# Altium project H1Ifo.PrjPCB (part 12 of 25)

## Sheet IfoIsc6.SchDoc: D1800185
size C; Engineer: Daniel Sigg; DocumentNumber: 11; Revision: 4; SheetNumber: 11; SheetTotal: 11
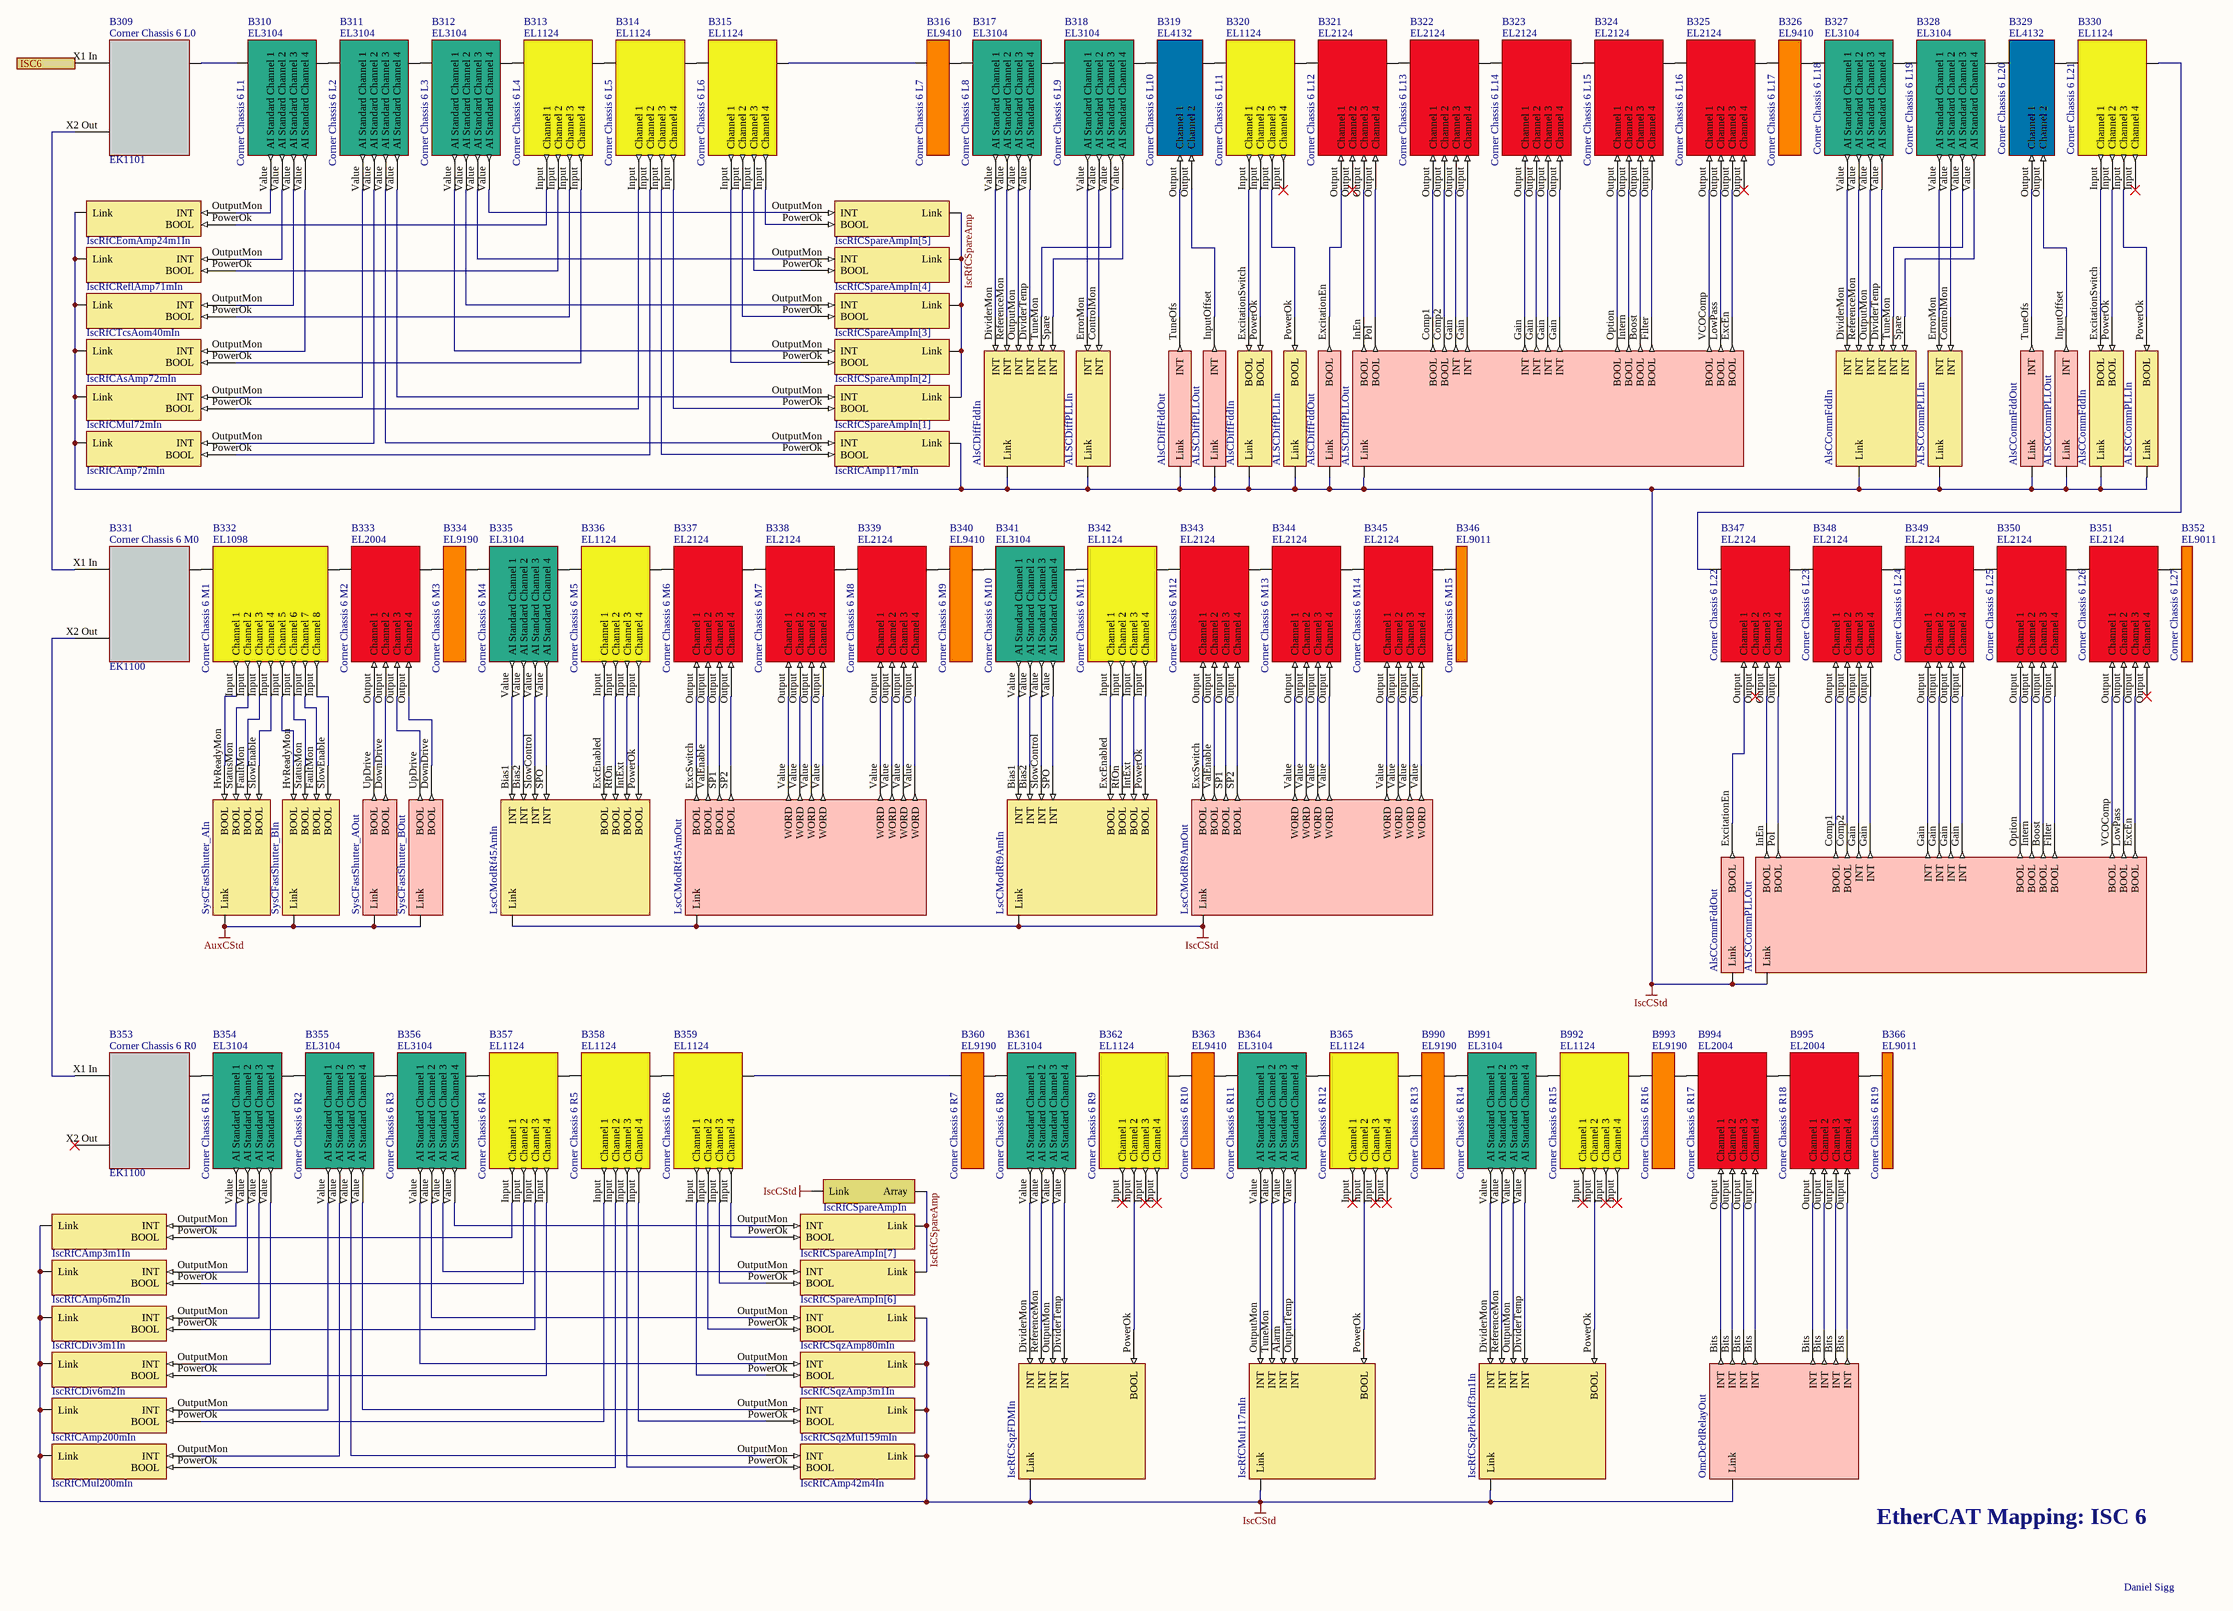
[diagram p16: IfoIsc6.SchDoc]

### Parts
B309  Corner Chassis 6 L0  Part Number: EK1101  (mechanical)
B310  Corner Chassis 6 L1  Part Number: EL3104  (mechanical)
B311  Corner Chassis 6 L2  Part Number: EL3104  (mechanical)
B312  Corner Chassis 6 L3  Part Number: EL3104  (mechanical)
B313  Corner Chassis 6 L4  Part Number: EL1124  (mechanical)
B314  Corner Chassis 6 L5  Part Number: EL1124  (mechanical)
B315  Corner Chassis 6 L6  Part Number: EL1124  (mechanical)
B316  Corner Chassis 6 L7  Part Number: EL9410  (mechanical)
B317  Corner Chassis 6 L8  Part Number: EL3104  (mechanical)
B318  Corner Chassis 6 L9  Part Number: EL3104  (mechanical)
B319  Corner Chassis 6 L10  Part Number: EL4132  (mechanical)
B320  Corner Chassis 6 L11  Part Number: EL1124  (mechanical)
B321  Corner Chassis 6 L12  Part Number: EL2124  (mechanical)
B322  Corner Chassis 6 L13  Part Number: EL2124  (mechanical)
B323  Corner Chassis 6 L14  Part Number: EL2124  (mechanical)
B324  Corner Chassis 6 L15  Part Number: EL2124  (mechanical)
B325  Corner Chassis 6 L16  Part Number: EL2124  (mechanical)
B326  Corner Chassis 6 L17  Part Number: EL9410  (mechanical)
B327  Corner Chassis 6 L18  Part Number: EL3104  (mechanical)
B328  Corner Chassis 6 L19  Part Number: EL3104  (mechanical)
B329  Corner Chassis 6 L20  Part Number: EL4132  (mechanical)
B330  Corner Chassis 6 L21  Part Number: EL1124  (mechanical)
B331  Corner Chassis 6 M0  Part Number: EK1100  (mechanical)
B332  Corner Chassis 6 M1  Part Number: EL1098  (mechanical)
B333  Corner Chassis 6 M2  Part Number: EL2004  (mechanical)
B334  Corner Chassis 6 M3  Part Number: EL9190  (mechanical)
B335  Corner Chassis 6 M4  Part Number: EL3104  (mechanical)
B336  Corner Chassis 6 M5  Part Number: EL1124  (mechanical)
B337  Corner Chassis 6 M6  Part Number: EL2124  (mechanical)
B338  Corner Chassis 6 M7  Part Number: EL2124  (mechanical)
B339  Corner Chassis 6 M8  Part Number: EL2124  (mechanical)
B340  Corner Chassis 6 M9  Part Number: EL9410  (mechanical)
B341  Corner Chassis 6 M10  Part Number: EL3104  (mechanical)
B342  Corner Chassis 6 M11  Part Number: EL1124  (mechanical)
B343  Corner Chassis 6 M12  Part Number: EL2124  (mechanical)
B344  Corner Chassis 6 M13  Part Number: EL2124  (mechanical)
B345  Corner Chassis 6 M14  Part Number: EL2124  (mechanical)
B346  Corner Chassis 6 M15  Part Number: EL9011  (mechanical)
B347  Corner Chassis 6 L22  Part Number: EL2124  (mechanical)
B348  Corner Chassis 6 L23  Part Number: EL2124  (mechanical)
B349  Corner Chassis 6 L24  Part Number: EL2124  (mechanical)
B350  Corner Chassis 6 L25  Part Number: EL2124  (mechanical)
B351  Corner Chassis 6 L26  Part Number: EL2124  (mechanical)
B352  Corner Chassis 6 L27  Part Number: EL9011  (mechanical)
B353  Corner Chassis 6 R0  Part Number: EK1100  (mechanical)
B354  Corner Chassis 6 R1  Part Number: EL3104  (mechanical)
B355  Corner Chassis 6 R2  Part Number: EL3104  (mechanical)
B356  Corner Chassis 6 R3  Part Number: EL3104  (mechanical)
B357  Corner Chassis 6 R4  Part Number: EL1124  (mechanical)
B358  Corner Chassis 6 R5  Part Number: EL1124  (mechanical)
B359  Corner Chassis 6 R6  Part Number: EL1124  (mechanical)
B360  Corner Chassis 6 R7  Part Number: EL9190  (mechanical)
B361  Corner Chassis 6 R8  Part Number: EL3104  (mechanical)
B362  Corner Chassis 6 R9  Part Number: EL1124  (mechanical)
B363  Corner Chassis 6 R10  Part Number: EL9410  (mechanical)
B364  Corner Chassis 6 R11  Part Number: EL3104  (mechanical)
B365  Corner Chassis 6 R12  Part Number: EL1124  (mechanical)
B366  Corner Chassis 6 R19  Part Number: EL9011  (mechanical)
B990  Corner Chassis 6 R13  Part Number: EL9190  (mechanical)
B991  Corner Chassis 6 R14  Part Number: EL3104  (mechanical)
B992  Corner Chassis 6 R15  Part Number: EL1124  (mechanical)
B993  Corner Chassis 6 R16  Part Number: EL9190  (mechanical)
B994  Corner Chassis 6 R17  Part Number: EL2004  (mechanical)
B995  Corner Chassis 6 R18  Part Number: EL2004  (mechanical)
V272  AlsCDiffFddIn  (parts A,B of 2)  (no BOM)
V273  AlsCDiffFddOut  (parts A,B of 2)  (no BOM)
V274  AlsCCommFddIn  (parts A,B of 2)  (no BOM)
V275  AlsCCommFddOut  (parts A,B of 2)  (no BOM)
V276  ALSCDiffPLLIn  (parts A,B of 2)  (no BOM)
V277  ALSCDiffPLLOut  (parts A,B of 2)  (no BOM)
V278  ALSCCommPLLIn  (parts A,B of 2)  (no BOM)
V279  ALSCCommPLLOut  (parts A,B of 2)  (no BOM)
V406  IscRfCEomAmp24m1In  (no BOM)
V407  IscRfCSpareAmpIn[5]  (no BOM)
V408  IscRfCReflAmp71mIn  (no BOM)
V409  IscRfCSpareAmpIn[4]  (no BOM)
V412  IscRfCTcsAom40mIn  (no BOM)
V413  IscRfCSpareAmpIn[3]  (no BOM)
V414  IscRfCAsAmp72mIn  (no BOM)
V415  IscRfCSpareAmpIn[2]  (no BOM)
V416  IscRfCMul72mIn  (no BOM)
V417  IscRfCSpareAmpIn[1]  (no BOM)
V418  IscRfCAmp72mIn  (no BOM)
V419  IscRfCAmp117mIn  (no BOM)
V420  SysCFastShutter_AIn  (no BOM)
V421  SysCFastShutter_AOut  (no BOM)
V422  LscCModRf45AmIn  (no BOM)
V424  LscCModRf45AmOut  (no BOM)
V426  LscCModRf9AmIn  (no BOM)
V428  LscCModRf9AmOut  (no BOM)
V429  IscRfCSpareAmpIn  (no BOM)
V430  IscRfCAmp3m1In  (no BOM)
V431  IscRfCSpareAmpIn[7]  (no BOM)
V432  IscRfCAmp6m2In  (no BOM)
V433  IscRfCSpareAmpIn[6]  (no BOM)
V434  IscRfCDiv3m1In  (no BOM)
V435  IscRfCSqzAmp80mIn  (no BOM)
V436  IscRfCDiv6m2In  (no BOM)
V438  IscRfCSqzAmp3m1In  (no BOM)
V439  IscRfCSqzFDMIn  (no BOM)
V440  IscRfCMul117mIn  (no BOM)
V441  IscRfCAmp200mIn  (no BOM)
V442  IscRfCSqzMul159mIn  (no BOM)
V443  IscRfCMul200mIn  (no BOM)
V444  IscRfCAmp42m4In  (no BOM)
V900  IscRfCSqzPickoff3m1In  (no BOM)
V901  OmcDcPdRelayOut  (no BOM)
V908  SysCFastShutter_BIn  (no BOM)
V909  SysCFastShutter_BOut  (no BOM)

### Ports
ISC6

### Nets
AuxCStd: V420.1(Link) V421.1(Link) V908.1(Link) V909.1(Link)
IscCStd: V272.0(Link) V272.1(Link) V273.0(Link) V273.1(Link) V274.0(Link) V274.1(Link) V275.0(Link) V275.1(Link) V276.0(Link) V276.1(Link) V277.0(Link) V277.1(Link) V278.0(Link) V278.1(Link) V279.0(Link) V279.1(Link) V406.?1(Link) V408.?1(Link) V412.?1(Link) V414.?1(Link) V416.?1(Link) V418.?1(Link) V419.?1(Link) V422.0(Link) V424.?1(Link) V426.0(Link) V428.?1(Link) V429.?1(Link) V430.?1(Link) V432.?1(Link) V434.?1(Link) V435.?1(Link) V436.?1(Link) V438.?1(Link) V439.0(Link) V440.0(Link) V441.?1(Link) V442.?1(Link) V443.?1(Link) V444.?1(Link) V900.0(Link) V901.1(Link)
IscRfCSpareAmp: V407.?1(Link) V409.?1(Link) V413.?1(Link) V415.?1(Link) V417.?1(Link) V429.?2(Array) V431.?1(Link) V433.?1(Link)
NetB275_X2 Out: B309.X1_In(A) ; port ISC6
NetB309_Ebus: B309.Ebus(B) B310.Ebus(A)
NetB309_X2 Out: B309.X2_Out(C) B331.X1_In(A)
NetB310_Ebus: B310.Ebus(B) B311.Ebus(A)
NetB310_Value: B310.Value(AI_Standard_Channel_1) V406.OutputMon(INT)
NetB310_Value: B310.Value(AI_Standard_Channel_2) V408.OutputMon(INT)  [a separate net that carries the same name]
NetB310_Value: B310.Value(AI_Standard_Channel_3) V412.OutputMon(INT)  [a separate net that carries the same name]
NetB310_Value: B310.Value(AI_Standard_Channel_4) V414.OutputMon(INT)  [a separate net that carries the same name]
NetB311_Ebus: B311.Ebus(B) B312.Ebus(A)
NetB311_Value: B311.Value(AI_Standard_Channel_1) V416.OutputMon(INT)
NetB311_Value: B311.Value(AI_Standard_Channel_2) V418.OutputMon(INT)  [a separate net that carries the same name]
NetB311_Value: B311.Value(AI_Standard_Channel_3) V419.OutputMon(INT)  [a separate net that carries the same name]
NetB311_Value: B311.Value(AI_Standard_Channel_4) V417.OutputMon(INT)  [a separate net that carries the same name]
NetB312_Ebus: B312.Ebus(B) B313.Ebus(A)
NetB312_Value: B312.Value(AI_Standard_Channel_1) V415.OutputMon(INT)
NetB312_Value: B312.Value(AI_Standard_Channel_2) V413.OutputMon(INT)  [a separate net that carries the same name]
NetB312_Value: B312.Value(AI_Standard_Channel_3) V409.OutputMon(INT)  [a separate net that carries the same name]
NetB312_Value: B312.Value(AI_Standard_Channel_4) V407.OutputMon(INT)  [a separate net that carries the same name]
NetB313_Ebus: B313.Ebus(B) B314.Ebus(A)
NetB313_Input: B313.Input(Channel_1) V406.PowerOk(BOOL)
NetB313_Input: B313.Input(Channel_2) V408.PowerOk(BOOL)  [a separate net that carries the same name]
NetB313_Input: B313.Input(Channel_3) V412.PowerOk(BOOL)  [a separate net that carries the same name]
NetB313_Input: B313.Input(Channel_4) V414.PowerOk(BOOL)  [a separate net that carries the same name]
NetB314_Ebus: B314.Ebus(B) B315.Ebus(A)
NetB314_Input: B314.Input(Channel_1) V416.PowerOk(BOOL)
NetB314_Input: B314.Input(Channel_2) V418.PowerOk(BOOL)  [a separate net that carries the same name]
NetB314_Input: B314.Input(Channel_3) V419.PowerOk(BOOL)  [a separate net that carries the same name]
NetB314_Input: B314.Input(Channel_4) V417.PowerOk(BOOL)  [a separate net that carries the same name]
NetB315_Ebus: B315.Ebus(B) B316.Ebus(A)
NetB315_Input: B315.Input(Channel_1) V415.PowerOk(BOOL)
NetB315_Input: B315.Input(Channel_2) V413.PowerOk(BOOL)  [a separate net that carries the same name]
NetB315_Input: B315.Input(Channel_3) V409.PowerOk(BOOL)  [a separate net that carries the same name]
NetB315_Input: B315.Input(Channel_4) V407.PowerOk(BOOL)  [a separate net that carries the same name]
NetB316_Ebus: B316.Ebus(B) B317.Ebus(A)
NetB317_Ebus: B317.Ebus(B) B318.Ebus(A)
NetB317_Value: B317.Value(AI_Standard_Channel_1) V272.DividerMon(INT)
NetB317_Value: B317.Value(AI_Standard_Channel_2) V272.ReferenceMon(INT)  [a separate net that carries the same name]
NetB317_Value: B317.Value(AI_Standard_Channel_3) V272.OutputMon(INT)  [a separate net that carries the same name]
NetB317_Value: B317.Value(AI_Standard_Channel_4) V272.DividerTemp(INT)  [a separate net that carries the same name]
NetB318_Ebus: B318.Ebus(B) B319.Ebus(A)
NetB318_Value: B318.Value(AI_Standard_Channel_1) V276.ErrorMon(INT)
NetB318_Value: B318.Value(AI_Standard_Channel_2) V276.ControlMon(INT)  [a separate net that carries the same name]
NetB318_Value: B318.Value(AI_Standard_Channel_3) V272.TuneMon(INT)  [a separate net that carries the same name]
NetB318_Value: B318.Value(AI_Standard_Channel_4) V272.Spare(INT)  [a separate net that carries the same name]
NetB319_Ebus: B319.Ebus(B) B320.Ebus(A)
NetB319_Output: B319.Output(Channel_1) V273.TuneOfs(INT)
NetB319_Output: B319.Output(Channel_2) V277.InputOffset(INT)  [a separate net that carries the same name]
NetB320_Ebus: B320.Ebus(B) B321.Ebus(A)
NetB320_Input: B320.Input(Channel_1) V272.ExcitationSwitch(BOOL)
NetB320_Input: B320.Input(Channel_2) V272.PowerOk(BOOL)  [a separate net that carries the same name]
NetB320_Input: B320.Input(Channel_3) V276.PowerOk(BOOL)  [a separate net that carries the same name]
NetB321_Ebus: B321.Ebus(B) B322.Ebus(A)
NetB321_Output: B321.Output(Channel_1) V273.ExcitationEn(BOOL)
NetB321_Output: B321.Output(Channel_3) V277.InEn(BOOL)  [a separate net that carries the same name]
NetB321_Output: B321.Output(Channel_4) V277.Pol(BOOL)  [a separate net that carries the same name]
NetB322_Ebus: B322.Ebus(B) B323.Ebus(A)
NetB322_Output: B322.Output(Channel_1) V277.Comp1(BOOL)
NetB322_Output: B322.Output(Channel_2) V277.Comp2(BOOL)  [a separate net that carries the same name]
NetB322_Output: B322.Output(Channel_3) V277.Gain(INT)  [a separate net that carries the same name]
NetB322_Output: B322.Output(Channel_4) V277.Gain(INT)  [a separate net that carries the same name]
NetB323_Ebus: B323.Ebus(B) B324.Ebus(A)
NetB323_Output: B323.Output(Channel_1) V277.Gain(INT)
NetB323_Output: B323.Output(Channel_2) V277.Gain(INT)  [a separate net that carries the same name]
NetB323_Output: B323.Output(Channel_3) V277.Gain(INT)  [a separate net that carries the same name]
NetB323_Output: B323.Output(Channel_4) V277.Gain(INT)  [a separate net that carries the same name]
NetB324_Ebus: B324.Ebus(B) B325.Ebus(A)
NetB324_Output: B324.Output(Channel_1) V277.Option(BOOL)
NetB324_Output: B324.Output(Channel_2) V277.Intern(BOOL)  [a separate net that carries the same name]
NetB324_Output: B324.Output(Channel_3) V277.Boost(BOOL)  [a separate net that carries the same name]
NetB324_Output: B324.Output(Channel_4) V277.Filter(BOOL)  [a separate net that carries the same name]
NetB325_Ebus: B325.Ebus(B) B326.Ebus(A)
NetB325_Output: B325.Output(Channel_1) V277.VCOComp(BOOL)
NetB325_Output: B325.Output(Channel_2) V277.LowPass(BOOL)  [a separate net that carries the same name]
NetB325_Output: B325.Output(Channel_3) V277.ExcEn(BOOL)  [a separate net that carries the same name]
NetB326_Ebus: B326.Ebus(B) B327.Ebus(A)
NetB327_Ebus: B327.Ebus(B) B328.Ebus(A)
NetB327_Value: B327.Value(AI_Standard_Channel_1) V274.DividerMon(INT)
NetB327_Value: B327.Value(AI_Standard_Channel_2) V274.ReferenceMon(INT)  [a separate net that carries the same name]
NetB327_Value: B327.Value(AI_Standard_Channel_3) V274.OutputMon(INT)  [a separate net that carries the same name]
NetB327_Value: B327.Value(AI_Standard_Channel_4) V274.DividerTemp(INT)  [a separate net that carries the same name]
NetB328_Ebus: B328.Ebus(B) B329.Ebus(A)
NetB328_Value: B328.Value(AI_Standard_Channel_1) V278.ErrorMon(INT)
NetB328_Value: B328.Value(AI_Standard_Channel_2) V278.ControlMon(INT)  [a separate net that carries the same name]
NetB328_Value: B328.Value(AI_Standard_Channel_3) V274.TuneMon(INT)  [a separate net that carries the same name]
NetB328_Value: B328.Value(AI_Standard_Channel_4) V274.Spare(INT)  [a separate net that carries the same name]
NetB329_Ebus: B329.Ebus(B) B330.Ebus(A)
NetB329_Output: B329.Output(Channel_1) V275.TuneOfs(INT)
NetB329_Output: B329.Output(Channel_2) V279.InputOffset(INT)  [a separate net that carries the same name]
NetB330_Ebus: B330.Ebus(B) B347.Ebus(A)
NetB330_Input: B330.Input(Channel_1) V274.ExcitationSwitch(BOOL)
NetB330_Input: B330.Input(Channel_2) V274.PowerOk(BOOL)  [a separate net that carries the same name]
NetB330_Input: B330.Input(Channel_3) V278.PowerOk(BOOL)  [a separate net that carries the same name]
NetB331_Ebus: B331.Ebus(B) B332.Ebus(A)
NetB331_X2 Out: B331.X2_Out(C) B353.X1_In(A)
NetB332_Ebus: B332.Ebus(B) B333.Ebus(A)
NetB332_Input: B332.Input(Channel_1) V420.HvReadyMon(BOOL)
NetB332_Input: B332.Input(Channel_2) V420.StatusMon(BOOL)  [a separate net that carries the same name]
NetB332_Input: B332.Input(Channel_3) V420.FaultMon(BOOL)  [a separate net that carries the same name]
NetB332_Input: B332.Input(Channel_4) V420.SlowEnable(BOOL)  [a separate net that carries the same name]
NetB332_Input: B332.Input(Channel_5) V908.HvReadyMon(BOOL)  [a separate net that carries the same name]
NetB332_Input: B332.Input(Channel_6) V908.StatusMon(BOOL)  [a separate net that carries the same name]
NetB332_Input: B332.Input(Channel_7) V908.FaultMon(BOOL)  [a separate net that carries the same name]
NetB332_Input: B332.Input(Channel_8) V908.SlowEnable(BOOL)  [a separate net that carries the same name]
NetB333_Ebus: B333.Ebus(B) B334.Ebus(A)
NetB333_Output: B333.Output(Channel_1) V421.UpDrive(BOOL)
NetB333_Output: B333.Output(Channel_2) V421.DownDrive(BOOL)  [a separate net that carries the same name]
NetB333_Output: B333.Output(Channel_3) V909.UpDrive(BOOL)  [a separate net that carries the same name]
NetB333_Output: B333.Output(Channel_4) V909.DownDrive(BOOL)  [a separate net that carries the same name]
NetB334_Ebus: B334.Ebus(B) B335.Ebus(A)
NetB335_Ebus: B335.Ebus(B) B336.Ebus(A)
NetB335_Value: B335.Value(AI_Standard_Channel_1) V422.Bias1(INT)
NetB335_Value: B335.Value(AI_Standard_Channel_2) V422.Bias2(INT)  [a separate net that carries the same name]
NetB335_Value: B335.Value(AI_Standard_Channel_3) V422.SlowControl(INT)  [a separate net that carries the same name]
NetB335_Value: B335.Value(AI_Standard_Channel_4) V422.SPO(INT)  [a separate net that carries the same name]
NetB336_Ebus: B336.Ebus(B) B337.Ebus(A)
NetB336_Input: B336.Input(Channel_1) V422.ExcEnabled(BOOL)
NetB336_Input: B336.Input(Channel_2) V422.RfOn(BOOL)  [a separate net that carries the same name]
NetB336_Input: B336.Input(Channel_3) V422.IntExt(BOOL)  [a separate net that carries the same name]
NetB336_Input: B336.Input(Channel_4) V422.PowerOk(BOOL)  [a separate net that carries the same name]
NetB337_Ebus: B337.Ebus(B) B338.Ebus(A)
NetB337_Output: B337.Output(Channel_1) V424.ExcSwitch(BOOL)
NetB337_Output: B337.Output(Channel_2) V424.ValEnable(BOOL)  [a separate net that carries the same name]
NetB337_Output: B337.Output(Channel_3) V424.SP1(BOOL)  [a separate net that carries the same name]
NetB337_Output: B337.Output(Channel_4) V424.SP2(BOOL)  [a separate net that carries the same name]
NetB338_Ebus: B338.Ebus(B) B339.Ebus(A)
NetB338_Output: B338.Output(Channel_1) V424.Value(WORD)
NetB338_Output: B338.Output(Channel_2) V424.Value(WORD)  [a separate net that carries the same name]
NetB338_Output: B338.Output(Channel_3) V424.Value(WORD)  [a separate net that carries the same name]
NetB338_Output: B338.Output(Channel_4) V424.Value(WORD)  [a separate net that carries the same name]
NetB339_Ebus: B339.Ebus(B) B340.Ebus(A)
NetB339_Output: B339.Output(Channel_1) V424.Value(WORD)
NetB339_Output: B339.Output(Channel_2) V424.Value(WORD)  [a separate net that carries the same name]
NetB339_Output: B339.Output(Channel_3) V424.Value(WORD)  [a separate net that carries the same name]
NetB339_Output: B339.Output(Channel_4) V424.Value(WORD)  [a separate net that carries the same name]
NetB340_Ebus: B340.Ebus(B) B341.Ebus(A)
NetB341_Ebus: B341.Ebus(B) B342.Ebus(A)
NetB341_Value: B341.Value(AI_Standard_Channel_1) V426.Bias1(INT)
NetB341_Value: B341.Value(AI_Standard_Channel_2) V426.Bias2(INT)  [a separate net that carries the same name]
NetB341_Value: B341.Value(AI_Standard_Channel_3) V426.SlowControl(INT)  [a separate net that carries the same name]
NetB341_Value: B341.Value(AI_Standard_Channel_4) V426.SPO(INT)  [a separate net that carries the same name]
NetB342_Ebus: B342.Ebus(B) B343.Ebus(A)
NetB342_Input: B342.Input(Channel_1) V426.ExcEnabled(BOOL)
NetB342_Input: B342.Input(Channel_2) V426.RfOn(BOOL)  [a separate net that carries the same name]
NetB342_Input: B342.Input(Channel_3) V426.IntExt(BOOL)  [a separate net that carries the same name]
NetB342_Input: B342.Input(Channel_4) V426.PowerOk(BOOL)  [a separate net that carries the same name]
NetB343_Ebus: B343.Ebus(B) B344.Ebus(A)
NetB343_Output: B343.Output(Channel_1) V428.ExcSwitch(BOOL)
NetB343_Output: B343.Output(Channel_2) V428.ValEnable(BOOL)  [a separate net that carries the same name]
NetB343_Output: B343.Output(Channel_3) V428.SP1(BOOL)  [a separate net that carries the same name]
NetB343_Output: B343.Output(Channel_4) V428.SP2(BOOL)  [a separate net that carries the same name]
NetB344_Ebus: B344.Ebus(B) B345.Ebus(A)
NetB344_Output: B344.Output(Channel_1) V428.Value(WORD)
NetB344_Output: B344.Output(Channel_2) V428.Value(WORD)  [a separate net that carries the same name]
NetB344_Output: B344.Output(Channel_3) V428.Value(WORD)  [a separate net that carries the same name]
NetB344_Output: B344.Output(Channel_4) V428.Value(WORD)  [a separate net that carries the same name]
NetB345_Ebus: B345.Ebus(B) B346.Ebus(A)
NetB345_Output: B345.Output(Channel_1) V428.Value(WORD)
NetB345_Output: B345.Output(Channel_2) V428.Value(WORD)  [a separate net that carries the same name]
NetB345_Output: B345.Output(Channel_3) V428.Value(WORD)  [a separate net that carries the same name]
NetB345_Output: B345.Output(Channel_4) V428.Value(WORD)  [a separate net that carries the same name]
NetB347_Ebus: B347.Ebus(B) B348.Ebus(A)
NetB347_Output: B347.Output(Channel_1) V275.ExcitationEn(BOOL)
NetB347_Output: B347.Output(Channel_3) V279.InEn(BOOL)  [a separate net that carries the same name]
NetB347_Output: B347.Output(Channel_4) V279.Pol(BOOL)  [a separate net that carries the same name]
NetB348_Ebus: B348.Ebus(B) B349.Ebus(A)
NetB348_Output: B348.Output(Channel_1) V279.Comp1(BOOL)
NetB348_Output: B348.Output(Channel_2) V279.Comp2(BOOL)  [a separate net that carries the same name]
NetB348_Output: B348.Output(Channel_3) V279.Gain(INT)  [a separate net that carries the same name]
NetB348_Output: B348.Output(Channel_4) V279.Gain(INT)  [a separate net that carries the same name]
NetB349_Ebus: B349.Ebus(B) B350.Ebus(A)
NetB349_Output: B349.Output(Channel_1) V279.Gain(INT)
NetB349_Output: B349.Output(Channel_2) V279.Gain(INT)  [a separate net that carries the same name]
NetB349_Output: B349.Output(Channel_3) V279.Gain(INT)  [a separate net that carries the same name]
NetB349_Output: B349.Output(Channel_4) V279.Gain(INT)  [a separate net that carries the same name]
NetB350_Ebus: B350.Ebus(B) B351.Ebus(A)
NetB350_Output: B350.Output(Channel_1) V279.Option(BOOL)
NetB350_Output: B350.Output(Channel_2) V279.Intern(BOOL)  [a separate net that carries the same name]
NetB350_Output: B350.Output(Channel_3) V279.Boost(BOOL)  [a separate net that carries the same name]
NetB350_Output: B350.Output(Channel_4) V279.Filter(BOOL)  [a separate net that carries the same name]
NetB351_Ebus: B351.Ebus(B) B352.Ebus(A)
NetB351_Output: B351.Output(Channel_1) V279.VCOComp(BOOL)
NetB351_Output: B351.Output(Channel_2) V279.LowPass(BOOL)  [a separate net that carries the same name]
NetB351_Output: B351.Output(Channel_3) V279.ExcEn(BOOL)  [a separate net that carries the same name]
NetB353_Ebus: B353.Ebus(B) B354.Ebus(A)
NetB354_Ebus: B354.Ebus(B) B355.Ebus(A)
NetB354_Value: B354.Value(AI_Standard_Channel_1) V430.OutputMon(INT)
NetB354_Value: B354.Value(AI_Standard_Channel_2) V432.OutputMon(INT)  [a separate net that carries the same name]
NetB354_Value: B354.Value(AI_Standard_Channel_3) V434.OutputMon(INT)  [a separate net that carries the same name]
NetB354_Value: B354.Value(AI_Standard_Channel_4) V436.OutputMon(INT)  [a separate net that carries the same name]
NetB355_Ebus: B355.Ebus(B) B356.Ebus(A)
NetB355_Value: B355.Value(AI_Standard_Channel_1) V441.OutputMon(INT)
NetB355_Value: B355.Value(AI_Standard_Channel_2) V443.OutputMon(INT)  [a separate net that carries the same name]
NetB355_Value: B355.Value(AI_Standard_Channel_3) V444.OutputMon(INT)  [a separate net that carries the same name]
NetB355_Value: B355.Value(AI_Standard_Channel_4) V442.OutputMon(INT)  [a separate net that carries the same name]
NetB356_Ebus: B356.Ebus(B) B357.Ebus(A)
NetB356_Value: B356.Value(AI_Standard_Channel_1) V438.OutputMon(INT)
NetB356_Value: B356.Value(AI_Standard_Channel_2) V435.OutputMon(INT)  [a separate net that carries the same name]
NetB356_Value: B356.Value(AI_Standard_Channel_3) V433.OutputMon(INT)  [a separate net that carries the same name]
NetB356_Value: B356.Value(AI_Standard_Channel_4) V431.OutputMon(INT)  [a separate net that carries the same name]
NetB357_Ebus: B357.Ebus(B) B358.Ebus(A)
NetB357_Input: B357.Input(Channel_1) V430.PowerOk(BOOL)
NetB357_Input: B357.Input(Channel_2) V432.PowerOk(BOOL)  [a separate net that carries the same name]
NetB357_Input: B357.Input(Channel_3) V434.PowerOk(BOOL)  [a separate net that carries the same name]
NetB357_Input: B357.Input(Channel_4) V436.PowerOk(BOOL)  [a separate net that carries the same name]
NetB358_Ebus: B358.Ebus(B) B359.Ebus(A)
NetB358_Input: B358.Input(Channel_1) V441.PowerOk(BOOL)
NetB358_Input: B358.Input(Channel_2) V443.PowerOk(BOOL)  [a separate net that carries the same name]
NetB358_Input: B358.Input(Channel_3) V444.PowerOk(BOOL)  [a separate net that carries the same name]
NetB358_Input: B358.Input(Channel_4) V442.PowerOk(BOOL)  [a separate net that carries the same name]
NetB359_Ebus: B359.Ebus(B) B360.Ebus(A)
NetB359_Input: B359.Input(Channel_1) V438.PowerOk(BOOL)
NetB359_Input: B359.Input(Channel_2) V435.PowerOk(BOOL)  [a separate net that carries the same name]
NetB359_Input: B359.Input(Channel_3) V433.PowerOk(BOOL)  [a separate net that carries the same name]
NetB359_Input: B359.Input(Channel_4) V431.PowerOk(BOOL)  [a separate net that carries the same name]
NetB360_Ebus: B360.Ebus(B) B361.Ebus(A)
NetB361_Ebus: B361.Ebus(B) B362.Ebus(A)
NetB361_Value: B361.Value(AI_Standard_Channel_1) V439.DividerMon(INT)
NetB361_Value: B361.Value(AI_Standard_Channel_2) V439.ReferenceMon(INT)  [a separate net that carries the same name]
NetB361_Value: B361.Value(AI_Standard_Channel_3) V439.OutputMon(INT)  [a separate net that carries the same name]
NetB361_Value: B361.Value(AI_Standard_Channel_4) V439.DividerTemp(INT)  [a separate net that carries the same name]
NetB362_Ebus: B362.Ebus(B) B363.Ebus(A)
NetB362_Input: B362.Input(Channel_1) V439.PowerOk(BOOL)
NetB363_Ebus: B363.Ebus(B) B364.Ebus(A)
NetB364_Ebus: B364.Ebus(B) B365.Ebus(A)
NetB364_Value: B364.Value(AI_Standard_Channel_1) V440.OutputMon(INT)
NetB364_Value: B364.Value(AI_Standard_Channel_2) V440.TuneMon(INT)  [a separate net that carries the same name]
NetB364_Value: B364.Value(AI_Standard_Channel_3) V440.Alarm(INT)  [a separate net that carries the same name]
NetB364_Value: B364.Value(AI_Standard_Channel_4) V440.OutputTemp(INT)  [a separate net that carries the same name]
NetB365_Ebus: B365.Ebus(B) B990.Ebus(A)
NetB365_Input: B365.Input(Channel_1) V440.PowerOk(BOOL)
NetB366_Ebus: B366.Ebus(A) B995.Ebus(B)
NetB990_Ebus: B990.Ebus(B) B991.Ebus(A)
NetB991_Ebus: B991.Ebus(B) B992.Ebus(A)
NetB991_Value: B991.Value(AI_Standard_Channel_1) V900.DividerMon(INT)
NetB991_Value: B991.Value(AI_Standard_Channel_2) V900.ReferenceMon(INT)  [a separate net that carries the same name]
NetB991_Value: B991.Value(AI_Standard_Channel_3) V900.OutputMon(INT)  [a separate net that carries the same name]
NetB991_Value: B991.Value(AI_Standard_Channel_4) V900.DividerTemp(INT)  [a separate net that carries the same name]
NetB992_Ebus: B992.Ebus(B) B993.Ebus(A)
NetB992_Input: B992.Input(Channel_1) V900.PowerOk(BOOL)
NetB993_Ebus: B993.Ebus(B) B994.Ebus(A)
NetB994_Ebus: B994.Ebus(B) B995.Ebus(A)
NetB994_Output: B994.Output(Channel_1) V901.Bits(INT)
NetB994_Output: B994.Output(Channel_2) V901.Bits(INT)  [a separate net that carries the same name]
NetB994_Output: B994.Output(Channel_3) V901.Bits(INT)  [a separate net that carries the same name]
NetB994_Output: B994.Output(Channel_4) V901.Bits(INT)  [a separate net that carries the same name]
NetB995_Output: B995.Output(Channel_1) V901.Bits(INT)
NetB995_Output: B995.Output(Channel_2) V901.Bits(INT)  [a separate net that carries the same name]
NetB995_Output: B995.Output(Channel_3) V901.Bits(INT)  [a separate net that carries the same name]
NetB995_Output: B995.Output(Channel_4) V901.Bits(INT)  [a separate net that carries the same name]

Not connected (* = marked no-connect by the designer): B353 X2 Out(C)*

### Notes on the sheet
- (near V901) EtherCAT Mapping: ISC 6
- Daniel Sigg

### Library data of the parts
B309 = CouplerEK1101: EtherCAT Coupler; Rail: Left; BoxNextB: GDAFAQDM; BoxNextC: ESHMFDTR; BoxPrev: TWOPCTGM; PortPrevFull: 1221/C; PortPrevShort: C 'X2 Out'; Fullname: TIID^Vertex ISC (EtherCAT)^Corner Chassis 6 L0 (EK1101); BoxPorts: Junction; BoxAddr: 1254; Disabled: False
B310 = TerminalEL3104: EtherCAT Terminal EL3104 4-chn Analog Input; Rail: Left; BoxNextB: SNLCUVPX; BoxPrev: OOGIUDKC; PortPrevFull: 1254/B; PortPrevShort: B; Fullname: TIID^Vertex ISC (EtherCAT)^Corner Chassis 6 L0 (EK1101)^Corner Chassis 6 L1 (EL3104); BoxAddr: 1255; Disabled: False
B311 = TerminalEL3104: EtherCAT Terminal EL3104 4-chn Analog Input; Rail: Left; BoxNextB: PRXQVNQU; BoxPrev: GDAFAQDM; PortPrevFull: 1255/B; PortPrevShort: B; Fullname: TIID^Vertex ISC (EtherCAT)^Corner Chassis 6 L0 (EK1101)^Corner Chassis 6 L2 (EL3104); BoxAddr: 1256; Disabled: False
B312 = TerminalEL3104: EtherCAT Terminal EL3104 4-chn Analog Input; Rail: Left; BoxNextB: KRVHHBFD; BoxPrev: SNLCUVPX; PortPrevFull: 1256/B; PortPrevShort: B; Fullname: TIID^Vertex ISC (EtherCAT)^Corner Chassis 6 L0 (EK1101)^Corner Chassis 6 L3 (EL3104); BoxAddr: 1257; Disabled: False
B313 = TerminalEL1124: EtherCAT Terminal EL1124 4-chn Digital Input; Rail: Left; BoxNextB: TSVURDLP; BoxPrev: PRXQVNQU; PortPrevFull: 1257/B; PortPrevShort: B; Fullname: TIID^Vertex ISC (EtherCAT)^Corner Chassis 6 L0 (EK1101)^Corner Chassis 6 L4 (EL1124); BoxAddr: 1258; Disabled: False
B314 = TerminalEL1124: EtherCAT Terminal EL1124 4-chn Digital Input; Rail: Left; BoxNextB: LLYLSBXQ; BoxPrev: KRVHHBFD; PortPrevFull: 1258/B; PortPrevShort: B; Fullname: TIID^Vertex ISC (EtherCAT)^Corner Chassis 6 L0 (EK1101)^Corner Chassis 6 L5 (EL1124); BoxAddr: 1259; Disabled: False
B315 = TerminalEL1124: EtherCAT Terminal EL1124 4-chn Digital Input; Rail: Left; BoxNextB: KGMRAKCQ; BoxPrev: TSVURDLP; PortPrevFull: 1259/B; PortPrevShort: B; Fullname: TIID^Vertex ISC (EtherCAT)^Corner Chassis 6 L0 (EK1101)^Corner Chassis 6 L6 (EL1124); BoxAddr: 1260; Disabled: False
B316 = TerminalEL9410: EtherCAT Terminal EL9410 Power; Rail: Left; BoxNextB: BEYKWCFC; BoxPrev: LLYLSBXQ; PortPrevFull: 1260/B; PortPrevShort: B; Fullname: TIID^Vertex ISC (EtherCAT)^Corner Chassis 6 L0 (EK1101)^Corner Chassis 6 L7 (EL9410); BoxAddr: 1261; Disabled: False
B317 = TerminalEL3104: EtherCAT Terminal EL3104 4-chn Analog Input; Rail: Left; BoxNextB: DVIGSCFH; BoxPrev: KGMRAKCQ; PortPrevFull: 1261/B; PortPrevShort: B; Fullname: TIID^Vertex ISC (EtherCAT)^Corner Chassis 6 L0 (EK1101)^Corner Chassis 6 L8 (EL3104); BoxAddr: 1262; Disabled: False
B318 = TerminalEL3104: EtherCAT Terminal EL3104 4-chn Analog Input; Rail: Left; BoxNextB: UCPJYUEJ; BoxPrev: BEYKWCFC; PortPrevFull: 1262/B; PortPrevShort: B; Fullname: TIID^Vertex ISC (EtherCAT)^Corner Chassis 6 L0 (EK1101)^Corner Chassis 6 L9 (EL3104); BoxAddr: 1263; Disabled: False
B319 = TerminalEL4132: EtherCAT Terminal EL4132 2-chn Analog Ouput; Rail: Left; BoxNextB: CFSEXIDA; BoxPrev: DVIGSCFH; PortPrevFull: 1263/B; PortPrevShort: B; Fullname: TIID^Vertex ISC (EtherCAT)^Corner Chassis 6 L0 (EK1101)^Corner Chassis 6 L10 (EL4132); BoxAddr: 1264; Disabled: False
B320 = TerminalEL1124: EtherCAT Terminal EL1124 4-chn Digital Input; Rail: Left; BoxNextB: DIWSSTJW; BoxPrev: UCPJYUEJ; PortPrevFull: 1264/B; PortPrevShort: B; Fullname: TIID^Vertex ISC (EtherCAT)^Corner Chassis 6 L0 (EK1101)^Corner Chassis 6 L11 (EL1124); BoxAddr: 1265; Disabled: False
B321 = TerminalEL2124: EtherCAT Terminal EL2124 4-chn Digital Ouput; Rail: Left; BoxNextB: WKVIXMQW; BoxPrev: CFSEXIDA; PortPrevFull: 1265/B; PortPrevShort: B; Fullname: TIID^Vertex ISC (EtherCAT)^Corner Chassis 6 L0 (EK1101)^Corner Chassis 6 L12 (EL2124); BoxAddr: 1266; Disabled: False
B322 = TerminalEL2124: EtherCAT Terminal EL2124 4-chn Digital Ouput; Rail: Left; BoxNextB: XHSCKTOU; BoxPrev: DIWSSTJW; PortPrevFull: 1266/B; PortPrevShort: B; Fullname: TIID^Vertex ISC (EtherCAT)^Corner Chassis 6 L0 (EK1101)^Corner Chassis 6 L13 (EL2124); BoxAddr: 1267; Disabled: False
B323 = TerminalEL2124: EtherCAT Terminal EL2124 4-chn Digital Ouput; Rail: Left; BoxNextB: EPAHBJLJ; BoxPrev: WKVIXMQW; PortPrevFull: 1267/B; PortPrevShort: B; Fullname: TIID^Vertex ISC (EtherCAT)^Corner Chassis 6 L0 (EK1101)^Corner Chassis 6 L14 (EL2124); BoxAddr: 1268; Disabled: False
B324 = TerminalEL2124: EtherCAT Terminal EL2124 4-chn Digital Ouput; Rail: Left; BoxNextB: PGLBMAHA; BoxPrev: XHSCKTOU; PortPrevFull: 1268/B; PortPrevShort: B; Fullname: TIID^Vertex ISC (EtherCAT)^Corner Chassis 6 L0 (EK1101)^Corner Chassis 6 L15 (EL2124); BoxAddr: 1269; Disabled: False
B325 = TerminalEL2124: EtherCAT Terminal EL2124 4-chn Digital Ouput; Rail: Left; BoxNextB: XVLLWTYV; BoxPrev: EPAHBJLJ; PortPrevFull: 1269/B; PortPrevShort: B; Fullname: TIID^Vertex ISC (EtherCAT)^Corner Chassis 6 L0 (EK1101)^Corner Chassis 6 L16 (EL2124); BoxAddr: 1270; Disabled: False
B326 = TerminalEL9410: EtherCAT Terminal EL9410 Power; Rail: Left; BoxNextB: RWFROQFN; BoxPrev: PGLBMAHA; PortPrevFull: 1270/B; PortPrevShort: B; Fullname: TIID^Vertex ISC (EtherCAT)^Corner Chassis 6 L0 (EK1101)^Corner Chassis 6 L17 (EL9410); BoxAddr: 1271; Disabled: False
B327 = TerminalEL3104: EtherCAT Terminal EL3104 4-chn Analog Input; Rail: Left; BoxNextB: LSIWDNRE; BoxPrev: XVLLWTYV; PortPrevFull: 1271/B; PortPrevShort: B; Fullname: TIID^Vertex ISC (EtherCAT)^Corner Chassis 6 L0 (EK1101)^Corner Chassis 6 L18 (EL3104); BoxAddr: 1272; Disabled: False
B328 = TerminalEL3104: EtherCAT Terminal EL3104 4-chn Analog Input; Rail: Left; BoxNextB: LBHWFDXY; BoxPrev: RWFROQFN; PortPrevFull: 1272/B; PortPrevShort: B; Fullname: TIID^Vertex ISC (EtherCAT)^Corner Chassis 6 L0 (EK1101)^Corner Chassis 6 L19 (EL3104); BoxAddr: 1273; Disabled: False
B329 = TerminalEL4132: EtherCAT Terminal EL4132 2-chn Analog Ouput; Rail: Left; BoxNextB: FKMAFPSN; BoxPrev: LSIWDNRE; PortPrevFull: 1273/B; PortPrevShort: B; Fullname: TIID^Vertex ISC (EtherCAT)^Corner Chassis 6 L0 (EK1101)^Corner Chassis 6 L20 (EL4132); BoxAddr: 1274; Disabled: False
B330 = TerminalEL1124: EtherCAT Terminal EL1124 4-chn Digital Input; Rail: Left; BoxNextB: OHBRMHBN; BoxPrev: LBHWFDXY; PortPrevFull: 1274/B; PortPrevShort: B; Fullname: TIID^Vertex ISC (EtherCAT)^Corner Chassis 6 L0 (EK1101)^Corner Chassis 6 L21 (EL1124); BoxAddr: 1275; Disabled: False
B331 = CouplerEK1100: EtherCAT Coupler; Rail: Middle; BoxNextB: FEJRAQWL; BoxNextC: OKHVTYIV; BoxPrev: OOGIUDKC; PortPrevFull: 1254/C; PortPrevShort: C 'X2 Out'; Fullname: TIID^Vertex ISC (EtherCAT)^Corner Chassis 6 M0 (EK1100); BoxPorts: Junction; BoxAddr: 1281; Disabled: False
B332 = TerminalEL1098: EtherCAT Terminal EL1098 8-channel digital input terminal 24 V DC, switching to negative potential; Disabled: False
B333 = TerminalEL2004: EtherCAT Terminal EL2004 4-channel digital output terminal 24 V DC, 0.5 A; Rail: Middle; BoxNextB: GURSYOLM; BoxPrev: FEJRAQWL; PortPrevFull: 1282/B; PortPrevShort: B; Fullname: TIID^Vertex ISC (EtherCAT)^Corner Chassis 6 M0 (EK1100)^Corner Chassis 6 M2 (EL2004); BoxAddr: 1283; Disabled: False
B334 = TerminalEL9190: EtherCAT Terminal EL9190 Supply; BoxType: TerminalPassive; Rail: Middle; BoxNextB: VMGJNWYJ; BoxPrev: UHJLGKNW; PortPrevShort: B; Fullname: TIID^Vertex ISC (EtherCAT)^Corner Chassis 6 M0 (EK1100)^Corner Chassis 6 M3 (EL9190); Disabled: False
B335 = TerminalEL3104: EtherCAT Terminal EL3104 4-chn Analog Input; Rail: Middle; BoxNextB: JGHHGDMP; BoxPrev: GURSYOLM; PortPrevFull: 1283/B; PortPrevShort: B; Fullname: TIID^Vertex ISC (EtherCAT)^Corner Chassis 6 M0 (EK1100)^Corner Chassis 6 M4 (EL3104); BoxAddr: 1284; Disabled: False
B336 = TerminalEL1124: EtherCAT Terminal EL1124 4-chn Digital Input; Rail: Middle; BoxNextB: GUQCLBBT; BoxPrev: VMGJNWYJ; PortPrevFull: 1284/B; PortPrevShort: B; Fullname: TIID^Vertex ISC (EtherCAT)^Corner Chassis 6 M0 (EK1100)^Corner Chassis 6 M5 (EL1124); BoxAddr: 1285; Disabled: False
B337 = TerminalEL2124: EtherCAT Terminal EL2124 4-chn Digital Ouput; Rail: Middle; BoxNextB: PIBEKQYG; BoxPrev: JGHHGDMP; PortPrevFull: 1285/B; PortPrevShort: B; Fullname: TIID^Vertex ISC (EtherCAT)^Corner Chassis 6 M0 (EK1100)^Corner Chassis 6 M6 (EL2124); BoxAddr: 1286; Disabled: False
B338 = TerminalEL2124: EtherCAT Terminal EL2124 4-chn Digital Ouput; Rail: Middle; BoxNextB: CQIJDUNI; BoxPrev: GUQCLBBT; PortPrevFull: 1286/B; PortPrevShort: B; Fullname: TIID^Vertex ISC (EtherCAT)^Corner Chassis 6 M0 (EK1100)^Corner Chassis 6 M7 (EL2124); BoxAddr: 1287; Disabled: False
B339 = TerminalEL2124: EtherCAT Terminal EL2124 4-chn Digital Ouput; Rail: Middle; BoxNextB: JJXKHQXA; BoxPrev: PIBEKQYG; PortPrevFull: 1287/B; PortPrevShort: B; Fullname: TIID^Vertex ISC (EtherCAT)^Corner Chassis 6 M0 (EK1100)^Corner Chassis 6 M8 (EL2124); BoxAddr: 1288; Disabled: False
B340 = TerminalEL9410: EtherCAT Terminal EL9410 Power; Rail: Middle; BoxNextB: UPBYQMBK; BoxPrev: CQIJDUNI; PortPrevFull: 1288/B; PortPrevShort: B; Fullname: TIID^Vertex ISC (EtherCAT)^Corner Chassis 6 M0 (EK1100)^Corner Chassis 6 M9 (EL9410); BoxAddr: 1289; Disabled: False
B341 = TerminalEL3104: EtherCAT Terminal EL3104 4-chn Analog Input; Rail: Middle; BoxNextB: BXSRAQDG; BoxPrev: JJXKHQXA; PortPrevFull: 1289/B; PortPrevShort: B; Fullname: TIID^Vertex ISC (EtherCAT)^Corner Chassis 6 M0 (EK1100)^Corner Chassis 6 M10 (EL3104); BoxAddr: 1290; Disabled: False
B342 = TerminalEL1124: EtherCAT Terminal EL1124 4-chn Digital Input; Rail: Middle; BoxNextB: EQWLOTWF; BoxPrev: UPBYQMBK; PortPrevFull: 1290/B; PortPrevShort: B; Fullname: TIID^Vertex ISC (EtherCAT)^Corner Chassis 6 M0 (EK1100)^Corner Chassis 6 M11 (EL1124); BoxAddr: 1291; Disabled: False
B343 = TerminalEL2124: EtherCAT Terminal EL2124 4-chn Digital Ouput; Rail: Middle; BoxNextB: TYIABFFT; BoxPrev: BXSRAQDG; PortPrevFull: 1291/B; PortPrevShort: B; Fullname: TIID^Vertex ISC (EtherCAT)^Corner Chassis 6 M0 (EK1100)^Corner Chassis 6 M12 (EL2124); BoxAddr: 1292; Disabled: False
B344 = TerminalEL2124: EtherCAT Terminal EL2124 4-chn Digital Ouput; Rail: Middle; BoxNextB: DYGUDJFP; BoxPrev: EQWLOTWF; PortPrevFull: 1292/B; PortPrevShort: B; Fullname: TIID^Vertex ISC (EtherCAT)^Corner Chassis 6 M0 (EK1100)^Corner Chassis 6 M13 (EL2124); BoxAddr: 1293; Disabled: False
B345 = TerminalEL2124: EtherCAT Terminal EL2124 4-chn Digital Ouput; Rail: Middle; BoxNextB: NIPPNCXR; BoxPrev: TYIABFFT; PortPrevFull: 1293/B; PortPrevShort: B; Fullname: TIID^Vertex ISC (EtherCAT)^Corner Chassis 6 M0 (EK1100)^Corner Chassis 6 M14 (EL2124); BoxAddr: 1294; Disabled: False
B346 = TerminalEL9011: EtherCAT Terminal EL9011 End; BoxType: TerminalPassive; Rail: Middle; BoxPrev: DYGUDJFP; PortPrevShort: B; Fullname: TIID^Vertex ISC (EtherCAT)^Corner Chassis 6 M0 (EK1100)^Corner Chassis 6 M15 (EL9011); Disabled: False
B347 = TerminalEL2124: EtherCAT Terminal EL2124 4-chn Digital Ouput; Rail: Left; BoxNextB: RXMHIYLO; BoxPrev: FKMAFPSN; PortPrevFull: 1275/B; PortPrevShort: B; Fullname: TIID^Vertex ISC (EtherCAT)^Corner Chassis 6 L0 (EK1101)^Corner Chassis 6 L22 (EL2124); BoxAddr: 1276; Disabled: False
B348 = TerminalEL2124: EtherCAT Terminal EL2124 4-chn Digital Ouput; Rail: Left; BoxNextB: AVOKPROJ; BoxPrev: OHBRMHBN; PortPrevFull: 1276/B; PortPrevShort: B; Fullname: TIID^Vertex ISC (EtherCAT)^Corner Chassis 6 L0 (EK1101)^Corner Chassis 6 L23 (EL2124); BoxAddr: 1277; Disabled: False
B349 = TerminalEL2124: EtherCAT Terminal EL2124 4-chn Digital Ouput; Rail: Left; BoxNextB: TGNQUVAF; BoxPrev: RXMHIYLO; PortPrevFull: 1277/B; PortPrevShort: B; Fullname: TIID^Vertex ISC (EtherCAT)^Corner Chassis 6 L0 (EK1101)^Corner Chassis 6 L24 (EL2124); BoxAddr: 1278; Disabled: False
B350 = TerminalEL2124: EtherCAT Terminal EL2124 4-chn Digital Ouput; Rail: Left; BoxNextB: PMKHMSLC; BoxPrev: AVOKPROJ; PortPrevFull: 1278/B; PortPrevShort: B; Fullname: TIID^Vertex ISC (EtherCAT)^Corner Chassis 6 L0 (EK1101)^Corner Chassis 6 L25 (EL2124); BoxAddr: 1279; Disabled: False
B351 = TerminalEL2124: EtherCAT Terminal EL2124 4-chn Digital Ouput; Rail: Left; BoxNextB: UPHQVVER; BoxPrev: TGNQUVAF; PortPrevFull: 1279/B; PortPrevShort: B; Fullname: TIID^Vertex ISC (EtherCAT)^Corner Chassis 6 L0 (EK1101)^Corner Chassis 6 L26 (EL2124); BoxAddr: 1280; Disabled: False
B352 = TerminalEL9011: EtherCAT Terminal EL9011 End; BoxType: TerminalPassive; Rail: Left; BoxPrev: PMKHMSLC; PortPrevShort: B; Fullname: TIID^Vertex ISC (EtherCAT)^Corner Chassis 6 L0 (EK1101)^Corner Chassis 6 L27 (EL9011); Disabled: False
B353 = CouplerEK1100: EtherCAT Coupler; Rail: Right; BoxNextB: RNUWTTAE; BoxPrev: ESHMFDTR; PortPrevFull: 1281/C; PortPrevShort: C 'X2 Out'; Fullname: TIID^Vertex ISC (EtherCAT)^Corner Chassis 6 R0 (EK1100); BoxPorts: Junction; BoxAddr: 1295; Disabled: False
B354 = TerminalEL3104: EtherCAT Terminal EL3104 4-chn Analog Input; Rail: Right; BoxNextB: OEHBOMYI; BoxPrev: OKHVTYIV; PortPrevFull: 1295/B; PortPrevShort: B; Fullname: TIID^Vertex ISC (EtherCAT)^Corner Chassis 6 R0 (EK1100)^Corner Chassis 6 R1 (EL3104); BoxAddr: 1296; Disabled: False
B355 = TerminalEL3104: EtherCAT Terminal EL3104 4-chn Analog Input; Rail: Right; BoxNextB: XHUOGMYW; BoxPrev: RNUWTTAE; PortPrevFull: 1296/B; PortPrevShort: B; Fullname: TIID^Vertex ISC (EtherCAT)^Corner Chassis 6 R0 (EK1100)^Corner Chassis 6 R2 (EL3104); BoxAddr: 1297; Disabled: False
B356 = TerminalEL3104: EtherCAT Terminal EL3104 4-chn Analog Input; Rail: Right; BoxNextB: DSDIUOIW; BoxPrev: OEHBOMYI; PortPrevFull: 1297/B; PortPrevShort: B; Fullname: TIID^Vertex ISC (EtherCAT)^Corner Chassis 6 R0 (EK1100)^Corner Chassis 6 R3 (EL3104); BoxAddr: 1298; Disabled: False
B357 = TerminalEL1124: EtherCAT Terminal EL1124 4-chn Digital Input; Rail: Right; BoxNextB: OSIDFKCF; BoxPrev: XHUOGMYW; PortPrevFull: 1298/B; PortPrevShort: B; Fullname: TIID^Vertex ISC (EtherCAT)^Corner Chassis 6 R0 (EK1100)^Corner Chassis 6 R4 (EL1124); BoxAddr: 1299; Disabled: False
B358 = TerminalEL1124: EtherCAT Terminal EL1124 4-chn Digital Input; Rail: Right; BoxNextB: LDDQUDJJ; BoxPrev: DSDIUOIW; PortPrevFull: 1299/B; PortPrevShort: B; Fullname: TIID^Vertex ISC (EtherCAT)^Corner Chassis 6 R0 (EK1100)^Corner Chassis 6 R5 (EL1124); BoxAddr: 1300; Disabled: False
B359 = TerminalEL1124: EtherCAT Terminal EL1124 4-chn Digital Input; Rail: Right; BoxNextB: CBOHLPOJ; BoxPrev: OSIDFKCF; PortPrevFull: 1300/B; PortPrevShort: B; Fullname: TIID^Vertex ISC (EtherCAT)^Corner Chassis 6 R0 (EK1100)^Corner Chassis 6 R6 (EL1124); BoxAddr: 1301; Disabled: False
B360 = TerminalEL9190: EtherCAT Terminal EL9190 Supply; BoxType: TerminalPassive; Rail: Right; BoxNextB: UQWPBLEB; BoxPrev: LDDQUDJJ; PortPrevShort: B; Fullname: TIID^Vertex ISC (EtherCAT)^Corner Chassis 6 R0 (EK1100)^Corner Chassis 6 R7 (EL9190); Disabled: False
B361 = TerminalEL3104: EtherCAT Terminal EL3104 4-chn Analog Input; Rail: Right; BoxNextB: IEFPOHWL; BoxPrev: CBOHLPOJ; PortPrevFull: 1301/B; PortPrevShort: B; Fullname: TIID^Vertex ISC (EtherCAT)^Corner Chassis 6 R0 (EK1100)^Corner Chassis 6 R8 (EL3104); BoxAddr: 1302; Disabled: False
B362 = TerminalEL1124: EtherCAT Terminal EL1124 4-chn Digital Input; Rail: Right; BoxNextB: UMBLXBOL; BoxPrev: UQWPBLEB; PortPrevFull: 1302/B; PortPrevShort: B; Fullname: TIID^Vertex ISC (EtherCAT)^Corner Chassis 6 R0 (EK1100)^Corner Chassis 6 R9 (EL1124); BoxAddr: 1303; Disabled: False
B363 = TerminalEL9410: EtherCAT Terminal EL9410 Power; Rail: Right; BoxNextB: GYPGOPGD; BoxPrev: IEFPOHWL; PortPrevFull: 1303/B; PortPrevShort: B; Fullname: TIID^Vertex ISC (EtherCAT)^Corner Chassis 6 R0 (EK1100)^Corner Chassis 6 R10 (EL9410); BoxAddr: 1304; Disabled: False
B364 = TerminalEL3104: EtherCAT Terminal EL3104 4-chn Analog Input; Rail: Right; BoxNextB: KBVOCMAB; BoxPrev: UMBLXBOL; PortPrevFull: 1304/B; PortPrevShort: B; Fullname: TIID^Vertex ISC (EtherCAT)^Corner Chassis 6 R0 (EK1100)^Corner Chassis 6 R11 (EL3104); BoxAddr: 1305; Disabled: False
B365 = TerminalEL1124: EtherCAT Terminal EL1124 4-chn Digital Input; Rail: Right; BoxNextB: FFOEUNXG; BoxPrev: GYPGOPGD; PortPrevFull: 1305/B; PortPrevShort: B; Fullname: TIID^Vertex ISC (EtherCAT)^Corner Chassis 6 R0 (EK1100)^Corner Chassis 6 R12 (EL1124); BoxAddr: 1306; Disabled: False
B366 = TerminalEL9011: EtherCAT Terminal EL9011 End; BoxType: TerminalPassive; Rail: Right; BoxPrev: JLBBMDFC; PortPrevShort: B; Fullname: TIID^Vertex ISC (EtherCAT)^Corner Chassis 6 R0 (EK1100)^Corner Chassis 6 R19 (EL9011); Disabled: False
B990 = TerminalEL9190: EtherCAT Terminal EL9190 Supply; BoxType: TerminalPassive; Rail: Right; BoxNextB: PKFXHGRT; BoxPrev: KBVOCMAB; PortPrevShort: B; Fullname: TIID^Vertex ISC (EtherCAT)^Corner Chassis 6 R0 (EK1100)^Corner Chassis 6 R13 (EL9190); Disabled: False
B991 = TerminalEL3104: EtherCAT Terminal EL3104 4-chn Analog Input; Rail: Right; BoxNextB: WBTLAAQF; BoxPrev: FFOEUNXG; PortPrevFull: 1306/B; PortPrevShort: B; Fullname: TIID^Vertex ISC (EtherCAT)^Corner Chassis 6 R0 (EK1100)^Corner Chassis 6 R14 (EL3104); BoxAddr: 1307; Disabled: False
B992 = TerminalEL1124: EtherCAT Terminal EL1124 4-chn Digital Input; Rail: Right; BoxNextB: KGRATEYJ; BoxPrev: PKFXHGRT; PortPrevFull: 1307/B; PortPrevShort: B; Fullname: TIID^Vertex ISC (EtherCAT)^Corner Chassis 6 R0 (EK1100)^Corner Chassis 6 R15 (EL1124); BoxAddr: 1308; Disabled: False
B993 = TerminalEL9190: EtherCAT Terminal EL9190 Supply; BoxType: TerminalPassive; Rail: Right; BoxNextB: VHOTHAJS; BoxPrev: WBTLAAQF; PortPrevShort: B; Fullname: TIID^Vertex ISC (EtherCAT)^Corner Chassis 6 R0 (EK1100)^Corner Chassis 6 R16 (EL9190); Disabled: False
B994 = TerminalEL2004: EtherCAT Terminal EL2004 4-channel digital output terminal 24 V DC, 0.5 A; Rail: Right; BoxNextB: JLBBMDFC; BoxPrev: KGRATEYJ; PortPrevFull: 1308/B; PortPrevShort: B; Fullname: TIID^Vertex ISC (EtherCAT)^Corner Chassis 6 R0 (EK1100)^Corner Chassis 6 R17 (EL2004); BoxAddr: 1309; Disabled: False
B995 = TerminalEL2004: EtherCAT Terminal EL2004 4-channel digital output terminal 24 V DC, 0.5 A; Rail: Right; BoxNextB: FIHQFTYG; BoxPrev: VHOTHAJS; PortPrevFull: 1309/B; PortPrevShort: B; Fullname: TIID^Vertex ISC (EtherCAT)^Corner Chassis 6 R0 (EK1100)^Corner Chassis 6 R18 (EL2004); BoxAddr: 1310; Disabled: False
V272 V274 = LowNoiseVco_FDD: LowNoiseVcoInStruct; BoxType: Variable; Instance: H1IscCorner Instance; PLC: H1IscCorner; Task: IscCStd
V273 V275 = LowNoiseVco_LowNoiseVcoOutStruct: LowNoiseVcoOutStruct; BoxType: Variable; Instance: H1IscCorner Instance; PLC: H1IscCorner; Task: IscCStd
V276 V278 = PLLforVCO_PLLforVCOInStruct: PLLforVCOInStruct; BoxType: Variable; Instance: H1IscCorner Instance; PLC: H1IscCorner; Task: IscCStd
V277 V279 = PLLforVCO_PLLforVCOOutStruct: PLLforVCOOutStruct; BoxType: Variable; Instance: H1IscCorner Instance; PLC: H1IscCorner; Task: IscCStd
V406-V409 V412-V419 V430-V436 V438 V441-V444 = RFAmplifier_RFAmplifierInStruct: RFAmplifierInStruct; BoxType: Variable; Instance: H1IscCorner Instance; PLC: H1IscCorner; Task: IscCStd
V420 V908 = FastShutterControl_FastShutterControlInStruct: FastShutterControlInStruct; BoxType: Variable
V421 V909 = FastShutterControl_FastShutterControlOutStruct: FastShutterControlOutStruct; BoxType: Variable; Instance: H1AuxCorner Instance; PLC: H1AuxCorner; Task: AuxCStd
V422 V426 = EomDriver_EomDriverInStruct: EomDriverInStruct; BoxType: Variable; Instance: H1IscCorner Instance; PLC: H1IscCorner; Task: IscCStd
V424 V428 = EomDriver_EomDriverOutStruct: EomDriverOutStruct; BoxType: Variable; Instance: H1IscCorner Instance; PLC: H1IscCorner; Task: IscCStd
V429 = ArrayAggregatorIn: Array [1..7] Of RFAmplifierInStruct; Instance: H1IscCorner Instance; PLC: H1IscCorner; Task: IscCStd; Lower Bound: 1; Upper Bound: 7
V439 V900 = LowNoiseVco_FrequencyDifferenceMixer: LowNoiseVcoInStruct; BoxType: Variable; Instance: H1IscCorner Instance; PLC: H1IscCorner; Task: IscCStd
V440 = LowNoiseVco_FixedRatioFrequencySourceInStruct: FixedRatioFrequencySourceInStruct; BoxType: Variable; Instance: H1IscCorner Instance; PLC: H1IscCorner; Task: IscCStd
V901 = IscWhitening_WhiteningBitsOutStruct: WhiteningBitsOutStruct; BoxType: Variable; Instance: H1IscCorner Instance; PLC: H1IscCorner; Task: IscCStd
